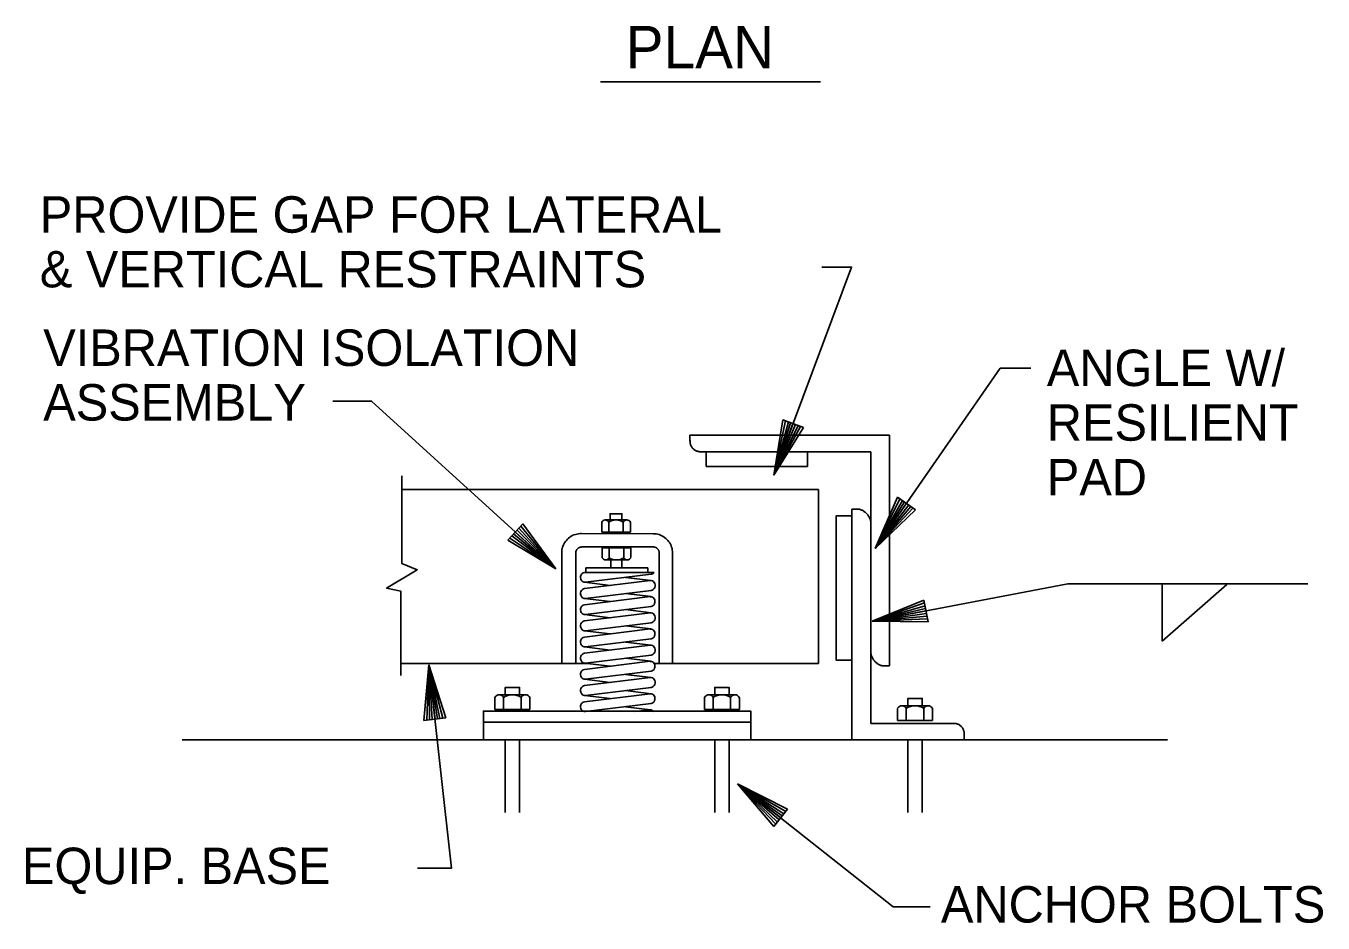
# Model space of a CAD drawing. Extents: x 10040.55 to 10045.84, y 10033.26 to 10035.76.
# Drawn here: x 10042.8093 to 10043.1654, y 10035.1901 to 10035.4364 of the extents above; entities that cross this region are included whole.
import ezdxf

# ---------------------------------------------------------------- set-up
doc = ezdxf.new("R2010")
doc.units = 0
doc.layers.add('Level 2', color=7, linetype='Continuous')

msp = doc.modelspace()

# ---------------------------------------------------------------- linework, layer by layer
at = {"layer": 'Level 2'}
for p, q in [((10042.96703, 10035.42111), (10043.02749, 10035.42111)), ((10043.01711, 10035.3283), (10043.01466, 10035.31315)), ((10043.01466, 10035.31315), (10043.01783, 10035.32803)), ((10043.01466, 10035.31315), (10043.01863, 10035.32776)), ((10043.01466, 10035.31315), (10043.01925, 10035.3275)), ((10043.01991, 10035.32727), (10043.01466, 10035.31315)), ((10043.01466, 10035.31315), (10043.02061, 10035.32699)), ((10043.01466, 10035.31315), (10043.02131, 10035.32674)), ((10043.01466, 10035.31315), (10043.02199, 10035.32648)), ((10043.02275, 10035.32618), (10043.01466, 10035.31315)), ((10043.01711, 10035.3283), (10043.02275, 10035.32618)), ((10043.04644, 10035.32408), (10042.99163, 10035.32408)), ((10042.99163, 10035.32408), (10042.99163, 10035.32241)), ((10043.04644, 10035.26072), (10043.04644, 10035.32408)), ((10042.99434, 10035.31954), (10043.04127, 10035.31954)), ((10043.04127, 10035.26431), (10043.04127, 10035.31954)), ((10043.02695, 10035.30914), (10042.91256, 10035.30914)), ((10043.02695, 10035.26139), (10043.02695, 10035.30914)), ((10043.04861, 10035.30707), (10043.0425, 10035.29299)), ((10043.0425, 10035.29299), (10043.04924, 10035.30664)), ((10043.0425, 10035.29299), (10043.04995, 10035.30618)), ((10043.0425, 10035.29299), (10043.05048, 10035.30577)), ((10043.05106, 10035.30539), (10043.0425, 10035.29299)), ((10043.0425, 10035.29299), (10043.05168, 10035.30495)), ((10043.0425, 10035.29299), (10043.0523, 10035.30453)), ((10043.04861, 10035.30707), (10043.05355, 10035.30363)), ((10042.96838, 10035.30081), (10042.97429, 10035.30081)), ((10043.0361, 10035.30378), (10043.0361, 10035.24042)), ((10043.03794, 10035.30378), (10043.0361, 10035.30378)), ((10043.0425, 10035.29299), (10043.05289, 10035.3041)), ((10043.05355, 10035.30363), (10043.0425, 10035.29299)), ((10042.94167, 10035.29528), (10042.94574, 10035.29973)), ((10042.94367, 10035.2975), (10042.95482, 10035.28736)), ((10042.95482, 10035.28736), (10042.94419, 10035.29804)), ((10042.95482, 10035.28736), (10042.94469, 10035.2986)), ((10042.95482, 10035.28736), (10042.94518, 10035.29914)), ((10042.94574, 10035.29973), (10042.95482, 10035.28736)), ((10042.96186, 10035.29708), (10042.98153, 10035.29704)), ((10042.96739, 10035.29747), (10042.96739, 10035.30022)), ((10042.96739, 10035.29747), (10042.97528, 10035.29747)), ((10042.96934, 10035.29747), (10042.96934, 10035.30022)), ((10042.97331, 10035.29747), (10042.97331, 10035.30022)), ((10042.97528, 10035.29747), (10042.97528, 10035.3002)), ((10043.04127, 10035.30019), (10043.04127, 10035.24496)), ((10042.94167, 10035.29528), (10042.95482, 10035.28736)), ((10042.95482, 10035.28736), (10042.94219, 10035.29585)), ((10042.95482, 10035.28736), (10042.94274, 10035.29649)), ((10042.95482, 10035.28736), (10042.94321, 10035.29697)), ((10042.95641, 10035.29172), (10042.95641, 10035.26139)), ((10042.96026, 10035.29181), (10042.96026, 10035.26139)), ((10042.96193, 10035.29339), (10042.98154, 10035.29339)), ((10042.96751, 10035.29319), (10042.97541, 10035.29319)), ((10042.96751, 10035.29319), (10042.96751, 10035.29044)), ((10042.96947, 10035.29319), (10042.96947, 10035.29044)), ((10042.97344, 10035.29319), (10042.97344, 10035.29044)), ((10042.97541, 10035.29319), (10042.97541, 10035.29046)), ((10042.98316, 10035.29172), (10042.98316, 10035.26139)), ((10042.98685, 10035.29172), (10042.98685, 10035.26139)), ((10042.96266, 10035.28641), (10042.98177, 10035.28641)), ((10042.98006, 10035.28766), (10042.96303, 10035.28766)), ((10042.96303, 10035.28766), (10042.96303, 10035.28641)), ((10042.9685, 10035.28984), (10042.97442, 10035.28984)), ((10042.96991, 10035.28988), (10042.96991, 10035.28764)), ((10042.97295, 10035.28764), (10042.97295, 10035.28988)), ((10042.98006, 10035.28766), (10042.98006, 10035.28641)), ((10042.96968, 10035.28283), (10042.96266, 10035.28369)), ((10042.96267, 10035.28197), (10042.9807, 10035.28419)), ((10042.96293, 10035.2837), (10042.98095, 10035.28592)), ((10042.98096, 10035.28419), (10042.97393, 10035.28505)), ((10043.09532, 10035.28328), (10043.04163, 10035.273)), ((10043.09532, 10035.28328), (10043.16126, 10035.28328)), ((10043.12121, 10035.28325), (10043.12121, 10035.2675)), ((10043.12121, 10035.2675), (10043.139, 10035.28313)), ((10042.96266, 10035.27753), (10042.98068, 10035.27975)), ((10042.96969, 10035.2784), (10042.96268, 10035.27925)), ((10042.96294, 10035.27926), (10042.98097, 10035.28148)), ((10042.98098, 10035.27975), (10042.97394, 10035.28061)), ((10042.96293, 10035.27482), (10042.98095, 10035.27704)), ((10042.98096, 10035.27531), (10042.97393, 10035.27618)), ((10043.05584, 10035.27878), (10043.04163, 10035.273)), ((10043.04163, 10035.273), (10043.05599, 10035.27803)), ((10043.04163, 10035.273), (10043.05617, 10035.27721)), ((10043.04163, 10035.273), (10043.05627, 10035.27654)), ((10043.05642, 10035.27585), (10043.04163, 10035.273)), ((10043.05584, 10035.27878), (10043.05697, 10035.27285)), ((10042.96968, 10035.27396), (10042.96266, 10035.27481)), ((10042.96267, 10035.27309), (10042.9807, 10035.27531)), ((10042.96294, 10035.27039), (10042.98097, 10035.2726)), ((10043.04163, 10035.273), (10043.05655, 10035.27511)), ((10043.04163, 10035.273), (10043.0567, 10035.27438)), ((10043.04163, 10035.273), (10043.05682, 10035.27367)), ((10043.05697, 10035.27285), (10043.04163, 10035.273)), ((10042.96266, 10035.26866), (10042.98068, 10035.27088)), ((10042.96969, 10035.26952), (10042.96268, 10035.27038)), ((10042.98098, 10035.27088), (10042.97394, 10035.27174)), ((10042.96968, 10035.26508), (10042.96266, 10035.26594)), ((10042.96267, 10035.26422), (10042.9807, 10035.26644)), ((10042.96293, 10035.26595), (10042.98095, 10035.26817)), ((10042.98096, 10035.26644), (10042.97393, 10035.2673)), ((10042.96266, 10035.25978), (10042.98068, 10035.262)), ((10042.96969, 10035.26065), (10042.96268, 10035.2615)), ((10042.96294, 10035.26151), (10042.98097, 10035.26373)), ((10042.98098, 10035.262), (10042.97394, 10035.26286)), ((10042.9635, 10035.26139), (10042.91228, 10035.26139)), ((10042.9186, 10035.24578), (10042.91993, 10035.26107)), ((10042.91993, 10035.26107), (10042.91942, 10035.24586)), ((10042.92164, 10035.2461), (10042.91993, 10035.26107)), ((10042.92459, 10035.24645), (10042.91993, 10035.26107)), ((10042.91993, 10035.26107), (10042.92015, 10035.24594)), ((10042.91993, 10035.26107), (10042.923, 10035.24625)), ((10042.91993, 10035.26107), (10042.92089, 10035.24603)), ((10042.91993, 10035.26107), (10042.92233, 10035.2462)), ((10042.91993, 10035.26107), (10042.92383, 10035.24636)), ((10042.96293, 10035.25707), (10042.98095, 10035.25928)), ((10042.98096, 10035.25755), (10042.97393, 10035.25842)), ((10043.02695, 10035.26139), (10042.98183, 10035.26139)), ((10043.0446, 10035.26072), (10043.04644, 10035.26072)), ((10042.96968, 10035.2562), (10042.96266, 10035.25706)), ((10042.96267, 10035.25534), (10042.9807, 10035.25755)), ((10042.96294, 10035.25264), (10042.98097, 10035.25484)), ((10042.9381, 10035.24876), (10042.9381, 10035.25209)), ((10042.9393, 10035.25282), (10042.94647, 10035.25282)), ((10042.94047, 10035.24876), (10042.94047, 10035.25209)), ((10042.94527, 10035.24876), (10042.94527, 10035.25209)), ((10042.94766, 10035.24876), (10042.94766, 10035.25207)), ((10042.96266, 10035.25091), (10042.98068, 10035.25311)), ((10042.96969, 10035.25176), (10042.96268, 10035.25263)), ((10042.98098, 10035.25311), (10042.97394, 10035.25398)), ((10042.99563, 10035.24876), (10042.99563, 10035.25209)), ((10042.99682, 10035.25282), (10043.00399, 10035.25282)), ((10042.99799, 10035.24876), (10042.99799, 10035.25209)), ((10043.00279, 10035.24876), (10043.00279, 10035.25209)), ((10043.00518, 10035.24876), (10043.00518, 10035.25207)), ((10042.9381, 10035.24876), (10042.94766, 10035.24876)), ((10042.96293, 10035.2482), (10042.98095, 10035.25041)), ((10042.98069, 10035.24872), (10042.97393, 10035.24954)), ((10042.97644, 10035.2482), (10042.98069, 10035.24872)), ((10042.99563, 10035.24876), (10043.00518, 10035.24876)), ((10043.04863, 10035.24575), (10043.04863, 10035.24908)), ((10043.04982, 10035.24981), (10043.05699, 10035.24981)), ((10043.05099, 10035.24575), (10043.05099, 10035.24908)), ((10043.05579, 10035.24575), (10043.05579, 10035.24908)), ((10043.05818, 10035.24575), (10043.05818, 10035.24906)), ((10042.92459, 10035.24645), (10042.9186, 10035.24578)), ((10042.93493, 10035.24525), (10043.00832, 10035.24525)), ((10043.06421, 10035.24496), (10043.04127, 10035.24496)), ((10043.04863, 10035.24575), (10043.05818, 10035.24575)), ((10042.85219, 10035.24042), (10043.12268, 10035.24042)), ((10042.94093, 10035.24043), (10042.94093, 10035.22045)), ((10042.94485, 10035.24043), (10042.94485, 10035.22045)), ((10042.99845, 10035.24043), (10042.99845, 10035.22045)), ((10043.00238, 10035.24043), (10043.00238, 10035.22045)), ((10043.0361, 10035.24042), (10043.06693, 10035.24042)), ((10043.05145, 10035.24043), (10043.05145, 10035.22045)), ((10043.05538, 10035.24043), (10043.05538, 10035.22045)), ((10043.06693, 10035.24042), (10043.06693, 10035.24209)), ((10043.01655, 10035.21903), (10043.00472, 10035.22835)), ((10043.01466, 10035.21666), (10043.00472, 10035.22835)), ((10043.0184, 10035.22139), (10043.00472, 10035.22835)), ((10043.00472, 10035.22835), (10043.01563, 10035.21785)), ((10043.00472, 10035.22835), (10043.01742, 10035.2201)), ((10043.00472, 10035.22835), (10043.01517, 10035.21729)), ((10043.00472, 10035.22835), (10043.01608, 10035.21845)), ((10043.00472, 10035.22835), (10043.01698, 10035.21959)), ((10043.00472, 10035.22835), (10043.01792, 10035.22078)), ((10043.0184, 10035.22139), (10043.01466, 10035.21666))]:
    msp.add_line(p, q, dxfattribs=at)
for points in [[(10043.02782, 10035.37023), (10043.03598, 10035.37023), (10043.01466, 10035.31315)], [(10043.08522, 10035.34245), (10043.07679, 10035.34245), (10043.0425, 10035.29299)], [(10042.89355, 10035.33346), (10042.90423, 10035.33346), (10042.95482, 10035.28736)], [(10042.99165, 10035.32261), (10042.99164, 10035.32243), (10042.99164, 10035.32223), (10042.99166, 10035.32204), (10042.99169, 10035.32184), (10042.99173, 10035.32166), (10042.99179, 10035.32147), (10042.99185, 10035.32129), (10042.99194, 10035.32111), (10042.99203, 10035.32094), (10042.99214, 10035.32078), (10042.99225, 10035.32063), (10042.99238, 10035.32047), (10042.99251, 10035.32033), (10042.99266, 10035.32021), (10042.99281, 10035.32008), (10042.99297, 10035.31998), (10042.99315, 10035.31988), (10042.99331, 10035.31979), (10042.9935, 10035.31972), (10042.99368, 10035.31966), (10042.99386, 10035.3196), (10042.99406, 10035.31957), (10042.99425, 10035.31954), (10042.99434, 10035.31954)], [(10042.9961, 10035.31943), (10042.9961, 10035.31551), (10043.02386, 10035.31551), (10043.02386, 10035.31958)], [(10042.91256, 10035.31296), (10042.91256, 10035.28881), (10042.91677, 10035.28713), (10042.90834, 10035.28206), (10042.91228, 10035.28122), (10042.91228, 10035.25807)], [(10042.97296, 10035.30083), (10042.97296, 10035.30249), (10042.96972, 10035.30249), (10042.96972, 10035.30083)], [(10043.0361, 10035.3019), (10043.03173, 10035.3019), (10043.03173, 10035.26232), (10043.0361, 10035.26232)], [(10043.03794, 10035.30378), (10043.03813, 10035.30373), (10043.03832, 10035.30368), (10043.03851, 10035.30361), (10043.0387, 10035.30354), (10043.03888, 10035.30346), (10043.03905, 10035.30336), (10043.03923, 10035.30327), (10043.0394, 10035.30317), (10043.03956, 10035.30305), (10043.03972, 10035.30293), (10043.03988, 10035.3028), (10043.04002, 10035.30266), (10043.04016, 10035.30252), (10043.04029, 10035.30238), (10043.04042, 10035.30222), (10043.04053, 10035.30205), (10043.04065, 10035.30189), (10043.04075, 10035.30172), (10043.04084, 10035.30154), (10043.04093, 10035.30136), (10043.04101, 10035.30118), (10043.04107, 10035.30099), (10043.04114, 10035.3008), (10043.04119, 10035.30061), (10043.04128, 10035.30019)], [(10042.96186, 10035.29708), (10042.96145, 10035.29707), (10042.96102, 10035.29702), (10042.96061, 10035.29694), (10042.96021, 10035.29682), (10042.95972, 10035.29668), (10042.95933, 10035.2965), (10042.95897, 10035.29629), (10042.95861, 10035.29606), (10042.95828, 10035.2958), (10042.95798, 10035.29551), (10042.95769, 10035.29521), (10042.95743, 10035.29488), (10042.9572, 10035.29452), (10042.95699, 10035.29416), (10042.95681, 10035.29377), (10042.95667, 10035.29338), (10042.95655, 10035.29297), (10042.95647, 10035.29256), (10042.95642, 10035.29215), (10042.95641, 10035.29172)], [(10042.98685, 10035.29172), (10042.98683, 10035.29214), (10042.98678, 10035.29255), (10042.98671, 10035.29296), (10042.98659, 10035.29336), (10042.98645, 10035.29376), (10042.98627, 10035.29414), (10042.98607, 10035.2945), (10042.98583, 10035.29484), (10042.98557, 10035.29518), (10042.98529, 10035.29548), (10042.98499, 10035.29576), (10042.98466, 10035.29602), (10042.98431, 10035.29625), (10042.98395, 10035.29646), (10042.98357, 10035.29664), (10042.98318, 10035.29678), (10042.98277, 10035.29689), (10042.98236, 10035.29697), (10042.98195, 10035.29702), (10042.98153, 10035.29704)], [(10042.96193, 10035.29339), (10042.96179, 10035.29338), (10042.96167, 10035.29336), (10042.96153, 10035.29334), (10042.96141, 10035.2933), (10042.96128, 10035.29326), (10042.96117, 10035.2932), (10042.96105, 10035.29314), (10042.96095, 10035.29306), (10042.96084, 10035.29299), (10042.96074, 10035.2929), (10042.96066, 10035.2928), (10042.96057, 10035.2927), (10042.9605, 10035.29258), (10042.96044, 10035.29247), (10042.96039, 10035.29235), (10042.96033, 10035.29223), (10042.9603, 10035.2921), (10042.96028, 10035.29198), (10042.96026, 10035.29184), (10042.96026, 10035.29181)], [(10042.98154, 10035.29339), (10042.98167, 10035.29339), (10042.98179, 10035.29336), (10042.98192, 10035.29334), (10042.98204, 10035.29331), (10042.98217, 10035.29327), (10042.98228, 10035.29322), (10042.9824, 10035.29316), (10042.9825, 10035.29308), (10042.9826, 10035.29301), (10042.9827, 10035.29292), (10042.98278, 10035.29282), (10042.98286, 10035.29273), (10042.98294, 10035.29263), (10042.983, 10035.29251), (10042.98305, 10035.2924), (10042.9831, 10035.29227), (10042.98314, 10035.29215), (10042.98316, 10035.29202), (10042.98318, 10035.2919), (10042.98318, 10035.29177)], [(10043.0446, 10035.26072), (10043.04442, 10035.26077), (10043.04422, 10035.26082), (10043.04403, 10035.26089), (10043.04384, 10035.26096), (10043.04367, 10035.26104), (10043.04349, 10035.26114), (10043.04331, 10035.26123), (10043.04315, 10035.26133), (10043.04298, 10035.26145), (10043.04282, 10035.26157), (10043.04267, 10035.2617), (10043.04252, 10035.26184), (10043.04239, 10035.26198), (10043.04225, 10035.26213), (10043.04213, 10035.26228), (10043.04201, 10035.26245), (10043.0419, 10035.26261), (10043.04179, 10035.26278), (10043.0417, 10035.26296), (10043.04161, 10035.26314), (10043.04153, 10035.26332), (10043.04147, 10035.26351), (10043.04141, 10035.2637), (10043.04135, 10035.26389), (10043.04126, 10035.26431)], [(10042.91679, 10035.20525), (10042.92621, 10035.20525), (10042.91993, 10035.26107)], [(10042.94485, 10035.25284), (10042.94485, 10035.25484), (10042.94093, 10035.25484), (10042.94093, 10035.25284)], [(10043.00238, 10035.25284), (10043.00238, 10035.25484), (10042.99845, 10035.25484), (10042.99845, 10035.25284)], [(10043.05538, 10035.24983), (10043.05538, 10035.25183), (10043.05145, 10035.25183), (10043.05145, 10035.24983)], [(10043.06691, 10035.24189), (10043.06692, 10035.24207), (10043.06692, 10035.24227), (10043.0669, 10035.24246), (10043.06686, 10035.24266), (10043.06682, 10035.24284), (10043.06676, 10035.24303), (10043.0667, 10035.24321), (10043.06661, 10035.24339), (10043.06652, 10035.24356), (10043.06642, 10035.24372), (10043.0663, 10035.24388), (10043.06618, 10035.24403), (10043.06604, 10035.24417), (10043.0659, 10035.24429), (10043.06574, 10035.24442), (10043.06558, 10035.24452), (10043.06541, 10035.24463), (10043.06524, 10035.24471), (10043.06505, 10035.24478), (10043.06488, 10035.24484), (10043.06469, 10035.2449), (10043.06449, 10035.24493), (10043.0643, 10035.24496), (10043.06421, 10035.24496)], [(10043.05755, 10035.19463), (10043.04744, 10035.19463), (10043.00472, 10035.22835)]]:
    msp.add_lwpolyline(points, dxfattribs=at)
msp.add_lwpolyline([(10043.00832, 10035.24043), (10042.93493, 10035.24043), (10042.93493, 10035.24835), (10043.00832, 10035.24835)], close=True, dxfattribs=at)
for centre, radius, start, end in [((10042.96837, 10035.29971), 0.0011, 27.8877, 152.0342), ((10042.97133, 10035.29717), 0.00365, 57.0062, 122.943), ((10042.97429, 10035.2997), 0.0011, 26.7827, 151.8391), ((10042.96849, 10035.29095), 0.0011, 207.9658, 332.1123), ((10042.97145, 10035.29349), 0.00365, 237.057, 302.9938), ((10042.97441, 10035.29095), 0.0011, 208.1609, 333.2173), ((10042.93929, 10035.25148), 0.00134, 27.8877, 152.0342), ((10042.94288, 10035.2484), 0.00441, 57.0062, 122.943), ((10042.94646, 10035.25147), 0.00134, 26.7827, 151.8391), ((10042.99682, 10035.25148), 0.00134, 27.8877, 152.0342), ((10043.0004, 10035.2484), 0.00441, 57.0062, 122.943), ((10043.00398, 10035.25147), 0.00134, 26.7827, 151.8391), ((10043.04982, 10035.24847), 0.00134, 27.8877, 152.0342), ((10043.0534, 10035.24539), 0.00441, 57.0062, 122.943), ((10043.05698, 10035.24846), 0.00134, 26.7827, 151.8391)]:
    msp.add_arc(centre, radius, start, end, dxfattribs=at)
for centre, major_axis, start_param, end_param in [((10042.96279, 10035.28505), (0, -0.00136), 3.251722, 6.393315), ((10042.98081, 10035.28726), (0, 0.00136), 3.251722, 4.030489), ((10042.98083, 10035.28283), (0, 0.00136), 3.251722, 6.393315), ((10042.96281, 10035.28061), (0, -0.00136), 3.251722, 6.393315), ((10042.98081, 10035.27839), (0, 0.00136), 3.251722, 6.393315), ((10042.96279, 10035.27617), (0, -0.00136), 3.251722, 6.393315), ((10042.96281, 10035.27173), (0, -0.00136), 3.251722, 6.393315), ((10042.98083, 10035.27395), (0, 0.00136), 3.251722, 6.393315), ((10042.96279, 10035.2673), (0, -0.00136), 3.251722, 6.393315), ((10042.98081, 10035.26951), (0, 0.00136), 3.251722, 6.393315), ((10042.98083, 10035.26508), (0, 0.00136), 3.251722, 6.393315), ((10042.96281, 10035.26286), (0, -0.00136), 3.251722, 6.393315), ((10042.98081, 10035.26064), (0, 0.00136), 3.251722, 6.393315), ((10042.96279, 10035.25842), (0, -0.00136), 3.251722, 6.393315), ((10042.96281, 10035.25398), (0, -0.00136), 3.251722, 6.393315), ((10042.98083, 10035.2562), (0, 0.00136), 3.251722, 6.393315), ((10042.96279, 10035.24955), (0, -0.00136), 3.251722, 6.393315), ((10042.98081, 10035.25176), (0, 0.00136), 3.251722, 6.393315), ((10042.98069, 10035.24736), (0, 0.00136), 5.361733, 6.39416)]:
    msp.add_ellipse(centre, major_axis=major_axis, ratio=0.9, start_param=start_param, end_param=end_param, dxfattribs=at)

# ---------------------------------------------------------------- texts
for s, height, p in [('PLAN', 0.011667, (10042.97396, 10035.42477)), ('PROVIDE GAP FOR LATERAL', 0.01, (10042.81315, 10035.37967)), ('& VERTICAL RESTRAINTS', 0.01, (10042.81315, 10035.36467)), ('VIBRATION ISOLATION', 0.01, (10042.8141, 10035.3431)), ('ANGLE W/', 0.01, (10043.08959, 10035.33757)), ('ASSEMBLY', 0.01, (10042.8141, 10035.3281)), ('RESILIENT ', 0.01, (10043.08959, 10035.32257)), ('PAD', 0.01, (10043.08959, 10035.30757)), ('EQUIP. BASE', 0.01, (10042.80825, 10035.20084)), ('ANCHOR BOLTS', 0.01, (10043.06052, 10035.19028))]:
    msp.add_text(s, height=height, dxfattribs=at).set_placement(p)

doc.saveas('drawing.dxf')
